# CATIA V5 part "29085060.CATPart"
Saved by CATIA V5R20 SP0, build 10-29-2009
Part number: 29085060
Definition: NONE
Nomenclature: 29085060
Source: Unknown
Description: 29085060
Bounding box of the stored display mesh (mm): x -30 to 44.548, y -56.5 to 91.048, z -46.5 to 46.5
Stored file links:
  C:\Users\Utente\Desktop\IO LAVORO\3D X SITO CF\X SITO\PLASTICA\RF1\29085060.CATPart
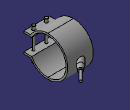
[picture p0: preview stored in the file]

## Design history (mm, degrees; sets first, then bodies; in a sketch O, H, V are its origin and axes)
Body1 "29085060" (main body)
  Solid1: solid without history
